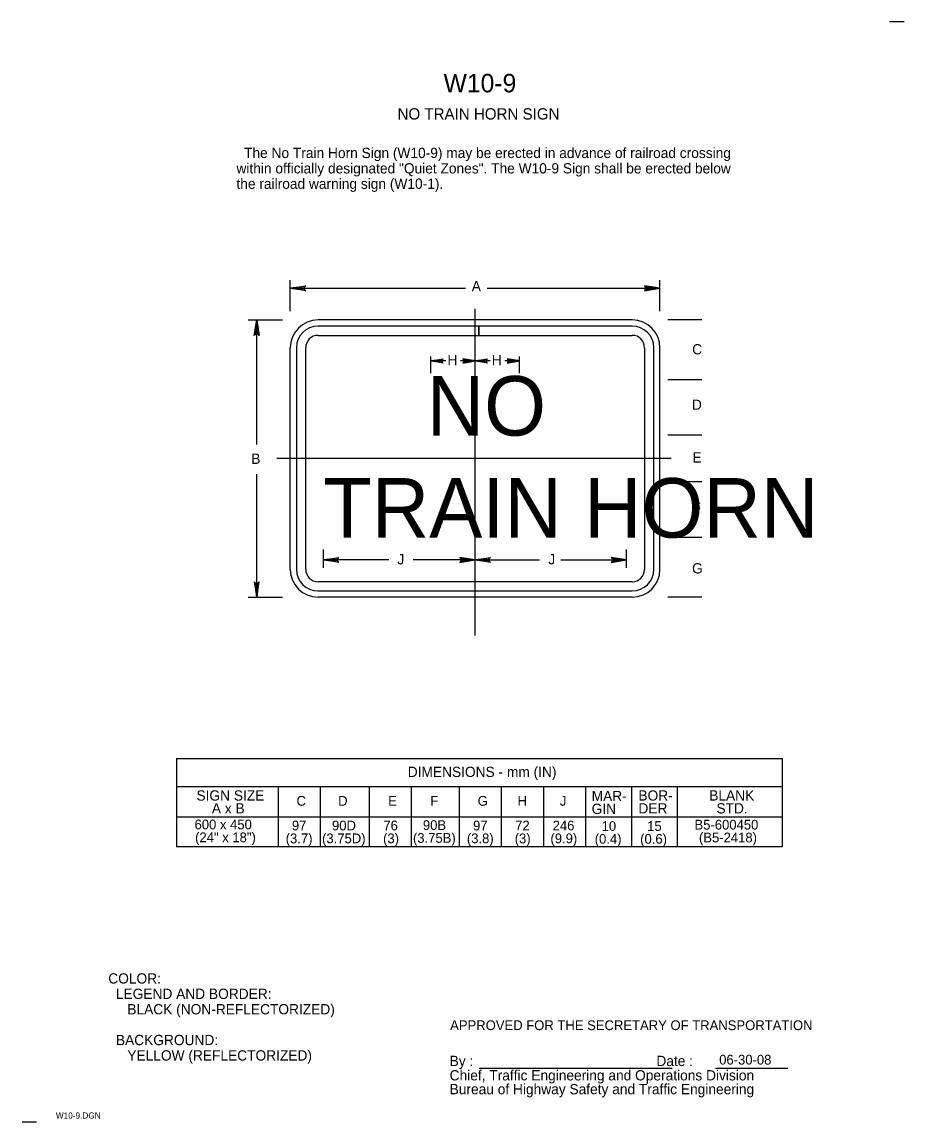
# Model space of a CAD drawing. Extents: x 0.004 to 0.219, y 0.004 to 0.272.
import ezdxf

# ---------------------------------------------------------------- set-up
doc = ezdxf.new("R2010")
doc.units = 0
for name, color, linetype in [('1', 7, 'Continuous'), ('2', 7, 'Continuous'), ('3', 7, 'Continuous'), ('63', 7, 'Continuous')]:
    doc.layers.add(name, color=color, linetype=linetype)

# ---------------------------------------------------------------- blocks, each defined once
blk = doc.blocks.new('RARROW')
at = {"layer": '3'}
for p, q in [((-2.156, 0.285), (-2.2665, 0.384625)), ((-2.2665, 0.384625), (0, 0)), ((0, 0), (-2.2665, -0.379125)), ((-2.156, 0.285), (-2.075625, 0.12075)), ((0, 0), (-2.156, 0.285)), ((-2.14975, -0.2705), (0, 0)), ((-2.075625, 0.12075), (0, 0)), ((0, 0), (-2.074, -0.108)), ((-2.2665, -0.379125), (-2.14975, -0.2705)), ((-2.074, -0.108), (-2.14975, -0.2705))]:
    blk.add_line(p, q, dxfattribs=at)

msp = doc.modelspace()

# ---------------------------------------------------------------- linework, layer by layer
at = {"layer": '1'}
for p, q in [((0.06945, 0.20131), (0.06945, 0.20885)), ((0.15945, 0.20131), (0.15945, 0.20885)), ((0.11445, 0.12237), (0.11445, 0.20194)), ((0.06129, 0.16883), (0.06129, 0.19919)), ((0.11534, 0.19769), (0.0762, 0.19769)), ((0.11534, 0.19769), (0.11534, 0.19544)), ((0.11534, 0.19544), (0.11534, 0.19769)), ((0.1527, 0.19769), (0.11534, 0.19769)), ((0.0762, 0.19544), (0.11534, 0.19544)), ((0.11534, 0.19544), (0.1527, 0.19544)), ((0.07095, 0.19244), (0.07095, 0.13844)), ((0.0732, 0.13844), (0.0732, 0.19244)), ((0.10365, 0.18625), (0.10365, 0.19033)), ((0.12525, 0.18625), (0.12525, 0.19033)), ((0.1557, 0.19244), (0.1557, 0.13844)), ((0.15795, 0.13844), (0.15795, 0.19244)), ((0.16222, 0.16544), (0.06618, 0.16544)), ((0.06129, 0.13169), (0.06129, 0.16162)), ((0.07755, 0.13886), (0.07755, 0.14326)), ((0.15135, 0.13886), (0.15135, 0.14326)), ((0.1527, 0.13544), (0.0762, 0.13544)), ((0.0762, 0.13319), (0.1527, 0.13319)), ((0.11544, 0.01695), (0.16242, 0.01695)), ((0.17295, 0.01695), (0.19056, 0.01695))]:
    msp.add_line(p, q, dxfattribs=at)
for centre, radius, start, end in [((0.0762, 0.19244), 0.00675, 90, 180), ((0.1527, 0.19244), 0.00675, 360, 90), ((0.0762, 0.19244), 0.00525, 90, 180), ((0.1527, 0.19244), 0.00525, 0, 90), ((0.0762, 0.19244), 0.003, 90, 180), ((0.1527, 0.19244), 0.003, 0, 90), ((0.0762, 0.13844), 0.00675, 180, 270), ((0.0762, 0.13844), 0.00525, 180, 270), ((0.0762, 0.13844), 0.003, 180, 270), ((0.1527, 0.13844), 0.00675, 270, 0), ((0.1527, 0.13844), 0.003, 270, 0), ((0.1527, 0.13844), 0.00525, 270, 0)]:
    msp.add_arc(centre, radius, start, end, dxfattribs=at)
at = {"layer": '3'}
for p, q in [((0.06945, 0.20692), (0.11208, 0.20692)), ((0.11741, 0.20692), (0.15945, 0.20692)), ((0.05921, 0.19919), (0.06754, 0.19919)), ((0.1527, 0.19919), (0.0762, 0.19919)), ((0.16969, 0.19919), (0.16136, 0.19919)), ((0.06945, 0.13844), (0.06945, 0.19244)), ((0.15945, 0.13844), (0.15945, 0.19244)), ((0.10733, 0.18921), (0.10365, 0.18921)), ((0.11445, 0.18921), (0.11089, 0.18921)), ((0.11813, 0.18921), (0.11445, 0.18921)), ((0.12525, 0.18921), (0.12169, 0.18921)), ((0.16969, 0.18464), (0.16136, 0.18464)), ((0.16969, 0.17114), (0.16136, 0.17114)), ((0.16969, 0.15974), (0.16136, 0.15974)), ((0.16969, 0.14624), (0.16136, 0.14624)), ((0.09341, 0.14075), (0.07755, 0.14075)), ((0.11445, 0.14075), (0.09937, 0.14075)), ((0.11445, 0.14075), (0.13012, 0.14075)), ((0.1353, 0.14075), (0.15135, 0.14075)), ((0.05921, 0.13169), (0.06754, 0.13169)), ((0.1527, 0.13169), (0.0762, 0.13169)), ((0.16969, 0.13169), (0.16136, 0.13169)), ((0.04172, 0.09239), (0.04172, 0.07089)), ((0.04176, 0.09238), (0.18925, 0.09238)), ((0.18925, 0.09238), (0.18925, 0.07088)), ((0.18925, 0.08551), (0.04172, 0.08551)), ((0.06651, 0.08551), (0.06651, 0.07089)), ((0.07672, 0.08551), (0.07672, 0.07089)), ((0.08865, 0.08551), (0.08865, 0.07089)), ((0.0989, 0.08551), (0.0989, 0.07089)), ((0.11058, 0.08551), (0.11058, 0.07089)), ((0.12083, 0.08551), (0.12083, 0.07089)), ((0.13108, 0.08551), (0.13108, 0.07089)), ((0.14133, 0.08551), (0.14133, 0.07089)), ((0.1525, 0.08551), (0.1525, 0.07088)), ((0.16362, 0.08551), (0.16362, 0.07088)), ((0.18925, 0.07814), (0.04172, 0.07814)), ((0.18925, 0.07089), (0.04172, 0.07089))]:
    msp.add_line(p, q, dxfattribs=at)
at = {"layer": '63'}
for p, q in [((0.21888, 0.27175), (0.21538, 0.27175)), ((0.21888, 0.27175), (0.21538, 0.27175)), ((0.00762, 0.00387), (0.00413, 0.00387)), ((0.00762, 0.00387), (0.00413, 0.00387))]:
    msp.add_line(p, q, dxfattribs=at)

# ---------------------------------------------------------------- block references
at = {"layer": '3'}
for p, xscale, yscale, rotation in [((0.06945, 0.20692), 0.001654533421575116, 0.0016366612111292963, 180), ((0.06129, 0.19919), 0.001654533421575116, 0.0016366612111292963, 89.99999999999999), ((0.10365, 0.18921), 0.001340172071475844, 0.00132569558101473, 180), ((0.11445, 0.18921), 0.001340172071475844, 0.00132569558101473, 180), ((0.07755, 0.14075), 0.001654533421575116, 0.0016366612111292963, 180), ((0.11445, 0.14075), 0.001654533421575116, 0.0016366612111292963, 180), ((0.06129, 0.13169), 0.001654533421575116, -0.0016366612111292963, -89.99999999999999)]:
    msp.add_blockref('RARROW', p, dxfattribs=dict(at, xscale=xscale, yscale=yscale, rotation=rotation))
for p, xscale, yscale in [((0.15945, 0.20692), 0.001654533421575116, -0.0016366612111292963), ((0.11453, 0.18921), 0.001340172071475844, -0.00132569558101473), ((0.12533, 0.18921), 0.001340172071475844, -0.00132569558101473), ((0.11445, 0.14075), 0.001654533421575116, -0.0016366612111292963), ((0.15135, 0.14075), 0.001654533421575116, -0.0016366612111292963)]:
    msp.add_blockref('RARROW', p, dxfattribs=dict(at, xscale=xscale, yscale=yscale))

# ---------------------------------------------------------------- texts
at = {"layer": '1'}
for s, height, p in [('W10-9', 0.0045, (0.10676, 0.25462)), ('NO TRAIN HORN SIGN', 0.0027503, (0.09556, 0.248)), ('TRAIN HORN', 0.014492, (0.07744, 0.14618)), ('COLOR:', 0.0025, (0.02513, 0.03759)), ('  LEGEND AND BORDER:', 0.0024998, (0.02513, 0.03384)), ('     BLACK (NON-REFLECTORIZED) ', 0.0024998, (0.02513, 0.03009)), ('APPROVED FOR THE SECRETARY OF TRANSPORTATION', 0.0023752, (0.10837, 0.02625)), ('  BACKGROUND:', 0.0024998, (0.02513, 0.02259)), ('     YELLOW (REFLECTORIZED)          ', 0.0024998, (0.02513, 0.01884)), ('By :                                                Date :', 0.0024998, (0.10825, 0.0175)), ('Chief, Traffic Engineering and Operations Division', 0.0024998, (0.10825, 0.014)), ('Bureau of Highway Safety and Traffic Engineering', 0.0024998, (0.10825, 0.01063)), ('W10-9.DGN', 0.0015, (0.01236, 0.0047))]:
    msp.add_text(s, height=height, dxfattribs=at).set_placement(p)
msp.add_text('NO', height=0.014492, rotation=360, dxfattribs=at).set_placement((0.10265, 0.17103))
at = {"layer": '2'}
for s, p in [('  The No Train Horn Sign (W10-9) may be erected in advance of railroad crossing ', (0.05634, 0.23862)), ('within officially designated "Quiet Zones". The W10-9 Sign shall be erected below', (0.05634, 0.23487)), ('the railroad warning sign (W10-1). ', (0.05634, 0.23112))]:
    msp.add_text(s, height=0.0024998, dxfattribs=at).set_placement(p)
at = {"layer": '3'}
for s, height, p in [('A', 0.0025, (0.11363, 0.20619)), ('C', 0.0025, (0.1673, 0.19081)), ('H', 0.0025, (0.1077, 0.18816)), ('H', 0.0025, (0.1185, 0.18816)), ('B', 0.0025, (0.05995, 0.16413)), ('J', 0.0025, (0.09551, 0.13966)), ('DIMENSIONS - mm (IN)', 0.0024998, (0.09805, 0.08789)), ('SIGN SIZE', 0.0025, (0.0466, 0.08214)), ('C', 0.00238, (0.07097, 0.08089)), ('D', 0.00238, (0.0811, 0.08089)), ('E', 0.00238, (0.09327, 0.08089)), ('F', 0.00238, (0.10352, 0.08089)), ('G', 0.00238, (0.11508, 0.08089)), ('J', 0.00238, (0.13509, 0.08089)), ('MAR-', 0.0025, (0.14283, 0.08201)), ('BOR-', 0.0025, (0.15421, 0.08214)), ('BLANK', 0.0025, (0.17146, 0.08214)), ('A x B', 0.0025, (0.05035, 0.07901)), ('GIN', 0.0025, (0.14283, 0.07889)), ('DER', 0.0025, (0.15421, 0.07901)), ('STD.', 0.0025, (0.17321, 0.07901)), ('600 x 450', 0.002375, (0.04614, 0.07514)), ('97', 0.002375, (0.06984, 0.07489)), ('90D', 0.002375, (0.07961, 0.07489)), ('76', 0.002375, (0.09211, 0.07489)), ('90B', 0.002375, (0.10173, 0.07499)), ('97', 0.002375, (0.11395, 0.07489)), ('246', 0.002375, (0.13333, 0.07489)), ('10', 0.002375, (0.14525, 0.07476)), ('B5-600450', 0.002375, (0.16787, 0.07509)), ('(24" x 18")', 0.0023752, (0.04627, 0.07201)), ('(3.7)', 0.002375, (0.06833, 0.07176)), ('(3.75D)', 0.002375, (0.07719, 0.07176)), ('(3)', 0.002375, (0.09204, 0.07176)), ('(3.75B)', 0.002375, (0.09932, 0.07186)), ('(3.8)', 0.002375, (0.11244, 0.07176)), ('(9.9)', 0.002375, (0.13279, 0.07176)), ('(0.4)', 0.002375, (0.14357, 0.07164)), ('(B5-2418)', 0.002375, (0.16895, 0.07197)), ('06-30-08', 0.002375, (0.17388, 0.01786))]:
    msp.add_text(s, height=height, dxfattribs=at).set_placement(p)
for s, height, p in [('D', 0.0025, (0.16723, 0.17731)), ('E', 0.0025, (0.16737, 0.16445)), ('F', 0.0025, (0.1674, 0.1522)), ('J', 0.0025, (0.13227, 0.13966)), ('G', 0.0025, (0.16728, 0.13746)), ('H', 0.00238, (0.12478, 0.08089)), ('72', 0.002375, (0.12421, 0.07489)), ('15', 0.002375, (0.15633, 0.07476)), ('(3)', 0.002375, (0.12409, 0.07176)), ('(0.6)', 0.002375, (0.15463, 0.07164))]:
    msp.add_text(s, height=height, rotation=360, dxfattribs=at).set_placement(p)

doc.saveas('drawing.dxf')
